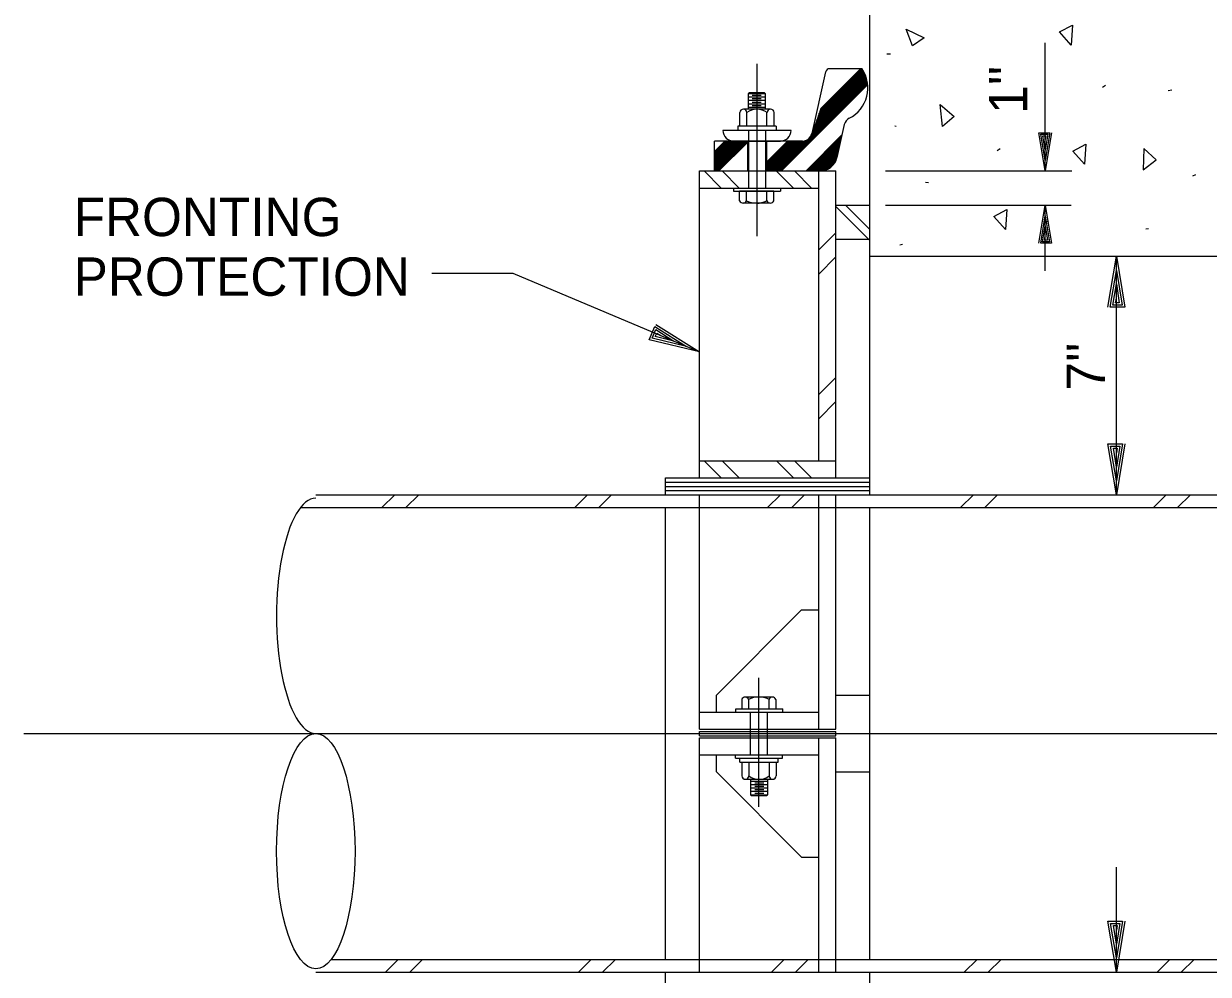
# Model space of a CAD drawing. Extents: x 22369.6 to 22389.4, y 22369.6 to 22386.
# Drawn here: x 22386.098 to 22387.546, y 22383.891 to 22385.053 of the extents above; entities that cross this region are included whole.
import ezdxf

# ---------------------------------------------------------------- set-up
doc = ezdxf.new("R2010")
doc.units = 0
for name, color, linetype in [('Level 1', 7, 'Continuous'), ('Level 2', 7, 'Continuous'), ('Level 4', 7, 'Continuous'), ('Level 44', 7, 'Continuous'), ('Level 50', 7, 'Continuous'), ('Level 7', 7, 'Continuous')]:
    doc.layers.add(name, color=color, linetype=linetype)

msp = doc.modelspace()

# ---------------------------------------------------------------- linework, layer by layer
at = {"layer": 'Level 1'}
for p, q in [((22387.3466, 22384.873), (22387.3466, 22385.0298)), ((22386.9944, 22385.0039), (22386.9944, 22384.7933)), ((22387.1271, 22384.9894), (22387.0643, 22384.9266)), ((22387.1269, 22384.9901), (22387.0648, 22384.928)), ((22387.1266, 22384.9908), (22387.0653, 22384.9294)), ((22387.1263, 22384.9914), (22387.0658, 22384.9309)), ((22387.126, 22384.992), (22387.0663, 22384.9323)), ((22387.1257, 22384.9927), (22387.0668, 22384.9337)), ((22387.1254, 22384.9933), (22387.0673, 22384.9352)), ((22387.1251, 22384.9939), (22387.0678, 22384.9366)), ((22387.1248, 22384.9945), (22387.0683, 22384.938)), ((22387.1245, 22384.9951), (22387.0688, 22384.9394)), ((22387.1241, 22384.9957), (22387.0693, 22384.9408)), ((22387.1238, 22384.9962), (22387.0698, 22384.9423)), ((22387.1234, 22384.9968), (22387.0703, 22384.9437)), ((22387.1231, 22384.9974), (22387.0708, 22384.9451)), ((22387.1227, 22384.9979), (22387.0713, 22384.9465)), ((22387.1219, 22384.998), (22387.0718, 22384.948)), ((22387.121, 22384.998), (22387.0723, 22384.9494)), ((22387.129, 22384.9832), (22387.0188, 22384.873)), ((22387.1291, 22384.9826), (22387.0195, 22384.873)), ((22387.1292, 22384.982), (22387.0202, 22384.873)), ((22387.1293, 22384.9814), (22387.0209, 22384.873)), ((22387.1294, 22384.9808), (22387.0216, 22384.873)), ((22387.1295, 22384.9802), (22387.0223, 22384.873)), ((22387.1296, 22384.9796), (22387.023, 22384.873)), ((22387.1296, 22384.9789), (22387.0237, 22384.873)), ((22387.1297, 22384.9783), (22387.0244, 22384.873)), ((22387.1288, 22384.9838), (22387.0596, 22384.9146)), ((22387.1287, 22384.9845), (22387.0608, 22384.9167)), ((22387.1285, 22384.9853), (22387.0613, 22384.9181)), ((22387.1283, 22384.986), (22387.0618, 22384.9195)), ((22387.1281, 22384.9867), (22387.0623, 22384.9209)), ((22387.1279, 22384.9874), (22387.0628, 22384.9223)), ((22387.1276, 22384.9881), (22387.0633, 22384.9238)), ((22387.1274, 22384.9888), (22387.0638, 22384.9252)), ((22386.984, 22384.9672), (22386.9851, 22384.9684)), ((22387.0049, 22384.9673), (22386.984, 22384.9673)), ((22386.984, 22384.9485), (22386.984, 22384.9672)), ((22387.0049, 22384.9631), (22386.984, 22384.9631)), ((22387.0038, 22384.9684), (22386.9851, 22384.9684)), ((22386.9996, 22384.9652), (22386.9887, 22384.9652)), ((22386.9996, 22384.9611), (22386.9887, 22384.9611)), ((22387.0049, 22384.9673), (22387.0038, 22384.9684)), ((22387.0049, 22384.9485), (22387.0049, 22384.9673)), ((22387.011, 22384.9485), (22386.9778, 22384.9485)), ((22387.0049, 22384.959), (22386.984, 22384.959)), ((22387.0049, 22384.9548), (22386.984, 22384.9548)), ((22387.0049, 22384.9506), (22386.984, 22384.9506)), ((22386.9996, 22384.9569), (22386.9887, 22384.9569)), ((22386.9996, 22384.9527), (22386.9887, 22384.9527)), ((22386.9736, 22384.9277), (22386.9736, 22384.9444)), ((22386.9736, 22384.9444), (22386.9736, 22384.9444)), ((22386.982, 22384.9277), (22386.982, 22384.9444)), ((22387.0067, 22384.9277), (22387.0067, 22384.9444)), ((22387.0153, 22384.9277), (22387.0153, 22384.9444)), ((22387.0179, 22384.9277), (22386.971, 22384.9277)), ((22386.971, 22384.9277), (22386.971, 22384.9225)), ((22386.984, 22384.9225), (22386.984, 22384.8522)), ((22387.0049, 22384.9225), (22387.0049, 22384.8522)), ((22387.0179, 22384.9277), (22387.0179, 22384.9225)), ((22387.0544, 22384.873), (22387.0983, 22384.917)), ((22386.9785, 22384.9095), (22386.9424, 22384.8734)), ((22386.9778, 22384.9095), (22386.9424, 22384.8741)), ((22386.9771, 22384.9095), (22386.9424, 22384.8748)), ((22386.9764, 22384.9095), (22386.9424, 22384.8755)), ((22386.9757, 22384.9095), (22386.9424, 22384.8762)), ((22386.975, 22384.9095), (22386.9424, 22384.8769)), ((22386.9743, 22384.9095), (22386.9424, 22384.8776)), ((22386.9735, 22384.9095), (22386.9424, 22384.8783)), ((22386.9728, 22384.9095), (22386.9424, 22384.879)), ((22386.9721, 22384.9095), (22386.9424, 22384.8797)), ((22386.9714, 22384.9095), (22386.9424, 22384.8804)), ((22386.9707, 22384.9095), (22386.9424, 22384.8811)), ((22386.97, 22384.9095), (22386.9424, 22384.8818)), ((22386.9693, 22384.9095), (22386.9424, 22384.8826)), ((22386.9686, 22384.9095), (22386.9424, 22384.8833)), ((22386.9679, 22384.9095), (22386.9424, 22384.884)), ((22386.9672, 22384.9095), (22386.9424, 22384.8847)), ((22386.9665, 22384.9095), (22386.9424, 22384.8854)), ((22386.9658, 22384.9095), (22386.9424, 22384.8861)), ((22386.9651, 22384.9095), (22386.9424, 22384.8868)), ((22386.9644, 22384.9095), (22386.9424, 22384.8875)), ((22386.9637, 22384.9095), (22386.9424, 22384.8882)), ((22386.9629, 22384.9095), (22386.9424, 22384.8889)), ((22386.9622, 22384.9095), (22386.9424, 22384.8896)), ((22386.9615, 22384.9095), (22386.9424, 22384.8903)), ((22386.9608, 22384.9095), (22386.9424, 22384.891)), ((22386.9601, 22384.9095), (22386.9424, 22384.8917)), ((22386.9594, 22384.9095), (22386.9424, 22384.8924)), ((22386.9587, 22384.9095), (22386.9424, 22384.8932)), ((22386.958, 22384.9095), (22386.9424, 22384.8939)), ((22386.9573, 22384.9095), (22386.9424, 22384.8946)), ((22386.9566, 22384.9095), (22386.9424, 22384.8953)), ((22386.9559, 22384.9095), (22386.9424, 22384.896)), ((22386.9552, 22384.9095), (22386.9424, 22384.8967)), ((22386.9792, 22384.9095), (22386.9428, 22384.873)), ((22386.9799, 22384.9095), (22386.9435, 22384.873)), ((22386.9806, 22384.9095), (22386.9442, 22384.873)), ((22386.9813, 22384.9095), (22386.9449, 22384.873)), ((22386.982, 22384.9095), (22386.9456, 22384.873)), ((22386.9827, 22384.9095), (22386.9463, 22384.873)), ((22386.9827, 22384.9088), (22386.947, 22384.873)), ((22386.9827, 22384.9081), (22386.9477, 22384.873)), ((22386.9827, 22384.908), (22386.9477, 22384.873)), ((22387.0425, 22384.9095), (22387.0061, 22384.873)), ((22387.0418, 22384.9095), (22387.0062, 22384.8739)), ((22387.0411, 22384.9095), (22387.0062, 22384.8746)), ((22387.0404, 22384.9095), (22387.0062, 22384.8753)), ((22387.0397, 22384.9095), (22387.0062, 22384.876)), ((22387.039, 22384.9095), (22387.0062, 22384.8767)), ((22387.0383, 22384.9095), (22387.0062, 22384.8774)), ((22387.0376, 22384.9095), (22387.0062, 22384.8781)), ((22387.0369, 22384.9095), (22387.0062, 22384.8788)), ((22387.0362, 22384.9095), (22387.0062, 22384.8795)), ((22387.0354, 22384.9095), (22387.0062, 22384.8802)), ((22387.0347, 22384.9095), (22387.0062, 22384.8809)), ((22387.034, 22384.9095), (22387.0062, 22384.8816)), ((22387.0333, 22384.9095), (22387.0062, 22384.8823)), ((22387.0326, 22384.9095), (22387.0062, 22384.883)), ((22387.0319, 22384.9095), (22387.0062, 22384.8837)), ((22387.0432, 22384.9095), (22387.0068, 22384.873)), ((22387.0439, 22384.9095), (22387.0075, 22384.873)), ((22387.0446, 22384.9095), (22387.0082, 22384.873)), ((22387.0454, 22384.9095), (22387.0089, 22384.873)), ((22387.0461, 22384.9095), (22387.0096, 22384.873)), ((22387.0468, 22384.9095), (22387.0103, 22384.873)), ((22387.0475, 22384.9095), (22387.011, 22384.873)), ((22387.0482, 22384.9095), (22387.0117, 22384.873)), ((22387.0489, 22384.9095), (22387.0124, 22384.873)), ((22387.0496, 22384.9095), (22387.0131, 22384.873)), ((22387.0503, 22384.9095), (22387.0138, 22384.873)), ((22387.051, 22384.9095), (22387.0145, 22384.873)), ((22387.0517, 22384.9095), (22387.0153, 22384.873)), ((22387.0528, 22384.9098), (22387.016, 22384.873)), ((22387.0538, 22384.9101), (22387.0167, 22384.873)), ((22387.0549, 22384.9106), (22387.0174, 22384.873)), ((22387.0566, 22384.9116), (22387.0181, 22384.873)), ((22387.0551, 22384.873), (22387.0981, 22384.9161)), ((22387.0558, 22384.873), (22387.0979, 22384.9152)), ((22387.0565, 22384.873), (22387.0977, 22384.9143)), ((22387.0572, 22384.873), (22387.0975, 22384.9133)), ((22387.0579, 22384.873), (22387.0973, 22384.9124)), ((22387.0586, 22384.873), (22387.0971, 22384.9115)), ((22387.0593, 22384.873), (22387.0969, 22384.9106)), ((22387.06, 22384.873), (22387.0967, 22384.9097)), ((22387.0607, 22384.873), (22387.0965, 22384.9088)), ((22387.0614, 22384.873), (22387.0963, 22384.9079)), ((22387.0621, 22384.873), (22387.0961, 22384.907)), ((22387.0628, 22384.873), (22387.0956, 22384.9058)), ((22387.0635, 22384.873), (22387.0957, 22384.9051)), ((22387.0643, 22384.873), (22387.0954, 22384.9042)), ((22387.065, 22384.873), (22387.0952, 22384.9033)), ((22387.0657, 22384.873), (22387.095, 22384.9024)), ((22387.0664, 22384.873), (22387.0948, 22384.9015)), ((22387.0671, 22384.873), (22387.0946, 22384.9006)), ((22387.0944, 22384.8997), (22387.0678, 22384.873)), ((22387.0942, 22384.8988), (22387.0685, 22384.873)), ((22387.094, 22384.8979), (22387.0692, 22384.873)), ((22387.0938, 22384.8969), (22387.0699, 22384.873)), ((22387.0936, 22384.896), (22387.0706, 22384.873)), ((22387.0934, 22384.8951), (22387.0714, 22384.8731)), ((22387.0932, 22384.8942), (22387.072, 22384.873)), ((22387.093, 22384.8933), (22387.0728, 22384.8731)), ((22387.0928, 22384.8924), (22387.0735, 22384.8731)), ((22387.0926, 22384.8915), (22387.0743, 22384.8732)), ((22387.0924, 22384.8906), (22387.0751, 22384.8733)), ((22387.0922, 22384.8896), (22387.076, 22384.8735)), ((22387.092, 22384.8887), (22387.0769, 22384.8737)), ((22387.0917, 22384.8878), (22387.0779, 22384.8739)), ((22387.0913, 22384.8867), (22387.079, 22384.8743)), ((22387.0907, 22384.8851), (22387.0805, 22384.875)), ((22387.0897, 22384.8832), (22387.0825, 22384.876)), ((22386.9506, 22384.8522), (22386.9298, 22384.873)), ((22386.9727, 22384.8522), (22386.9519, 22384.873)), ((22387.039, 22384.8522), (22387.0181, 22384.873)), ((22387.0611, 22384.8522), (22387.0402, 22384.873)), ((22387.1513, 22384.873), (22387.3791, 22384.873)), ((22386.9658, 22384.8522), (22386.9658, 22384.8483)), ((22386.9658, 22384.8483), (22387.0231, 22384.8483)), ((22387.015, 22384.8483), (22386.9733, 22384.8483)), ((22386.9733, 22384.8365), (22386.9733, 22384.8483)), ((22386.9817, 22384.8365), (22386.9817, 22384.8483)), ((22387.0064, 22384.8364), (22387.0064, 22384.8483)), ((22387.015, 22384.8365), (22387.015, 22384.8483)), ((22387.0231, 22384.8522), (22387.0231, 22384.8483)), ((22387.0107, 22384.8337), (22386.9775, 22384.8337)), ((22387.1325, 22384.8016), (22387.1027, 22384.8314)), ((22387.1513, 22384.8314), (22387.3783, 22384.8314)), ((22387.3466, 22384.7511), (22387.3466, 22384.8314)), ((22387.1325, 22384.7879), (22387.0908, 22384.8296)), ((22387.07, 22384.7765), (22387.0908, 22384.7973)), ((22387.07, 22384.747), (22387.0908, 22384.7679)), ((22387.4336, 22384.4772), (22387.4336, 22384.7689)), ((22387.07, 22384.5997), (22387.0908, 22384.6205)), ((22387.07, 22384.5702), (22387.0908, 22384.5911)), ((22386.9506, 22384.498), (22386.9298, 22384.5189)), ((22386.9727, 22384.498), (22386.9519, 22384.5189)), ((22387.039, 22384.498), (22387.0182, 22384.5189)), ((22387.061, 22384.498), (22387.0402, 22384.5189)), ((22386.8825, 22384.4928), (22387.1325, 22384.4928)), ((22386.8825, 22384.4876), (22387.1325, 22384.4876)), ((22386.5362, 22384.4616), (22386.5518, 22384.4772)), ((22386.5656, 22384.4616), (22386.5812, 22384.4772)), ((22386.7718, 22384.4616), (22386.7875, 22384.4772)), ((22386.8013, 22384.4616), (22386.8169, 22384.4772)), ((22386.8825, 22384.4824), (22387.1325, 22384.4824)), ((22387.0075, 22384.4616), (22387.0232, 22384.4772)), ((22387.037, 22384.4616), (22387.0526, 22384.4772)), ((22387.2433, 22384.4616), (22387.2589, 22384.4772)), ((22387.2727, 22384.4616), (22387.2883, 22384.4772)), ((22387.4789, 22384.4616), (22387.4946, 22384.4772)), ((22387.5084, 22384.4616), (22387.524, 22384.4772)), ((22386.9969, 22384.0958), (22386.9969, 22384.2534)), ((22386.9758, 22384.2272), (22386.9758, 22384.2155)), ((22387.0132, 22384.23), (22386.98, 22384.23)), ((22386.9842, 22384.2273), (22386.9842, 22384.2155)), ((22387.0089, 22384.2273), (22387.0089, 22384.2155)), ((22387.0175, 22384.2272), (22387.0175, 22384.2155)), ((22386.9686, 22384.2155), (22387.0259, 22384.2155)), ((22386.9686, 22384.2116), (22386.9686, 22384.2155)), ((22386.9865, 22384.1595), (22386.9865, 22384.2116)), ((22387.0074, 22384.1595), (22387.0074, 22384.2116)), ((22387.0259, 22384.2116), (22387.0259, 22384.2155)), ((22386.0985, 22384.1855), (22388.9892, 22384.1855)), ((22386.9241, 22384.1881), (22387.0908, 22384.1881)), ((22386.9241, 22384.1829), (22386.9241, 22384.1881)), ((22386.9241, 22384.1829), (22387.0908, 22384.1829)), ((22387.0908, 22384.1829), (22387.0908, 22384.1881)), ((22386.9683, 22384.1556), (22386.9683, 22384.1595)), ((22386.9683, 22384.1556), (22387.0256, 22384.1556)), ((22386.9735, 22384.1504), (22386.9735, 22384.1556)), ((22386.9735, 22384.1504), (22387.0204, 22384.1504)), ((22386.9761, 22384.1504), (22386.9761, 22384.1337)), ((22386.9847, 22384.1504), (22386.9847, 22384.1337)), ((22387.0094, 22384.1504), (22387.0094, 22384.1337)), ((22387.0178, 22384.1504), (22387.0178, 22384.1337)), ((22387.0204, 22384.1504), (22387.0204, 22384.1556)), ((22387.0256, 22384.1556), (22387.0256, 22384.1595)), ((22386.9804, 22384.1296), (22387.0136, 22384.1296)), ((22386.9865, 22384.1296), (22386.9865, 22384.1108)), ((22386.9865, 22384.1274), (22387.0074, 22384.1274)), ((22386.9865, 22384.1233), (22387.0074, 22384.1233)), ((22386.9918, 22384.1253), (22387.0027, 22384.1253)), ((22386.9918, 22384.1212), (22387.0027, 22384.1212)), ((22387.0074, 22384.1296), (22387.0074, 22384.1109)), ((22386.9865, 22384.1191), (22387.0074, 22384.1191)), ((22386.9865, 22384.1149), (22387.0074, 22384.1149)), ((22386.9865, 22384.1108), (22386.9876, 22384.1097)), ((22386.9865, 22384.1108), (22387.0074, 22384.1108)), ((22386.9876, 22384.1097), (22387.0063, 22384.1097)), ((22386.9918, 22384.117), (22387.0027, 22384.117)), ((22386.9918, 22384.1128), (22387.0027, 22384.1128)), ((22387.0074, 22384.1109), (22387.0063, 22384.1097)), ((22387.4336, 22383.8939), (22387.4336, 22384.0223)), ((22386.5406, 22383.8939), (22386.5562, 22383.9095)), ((22386.5701, 22383.8939), (22386.5857, 22383.9095)), ((22386.7763, 22383.8939), (22386.7919, 22383.9095)), ((22386.8058, 22383.8939), (22386.8214, 22383.9095)), ((22387.012, 22383.8939), (22387.0276, 22383.9095)), ((22387.0414, 22383.8939), (22387.0571, 22383.9095)), ((22387.2477, 22383.8939), (22387.2633, 22383.9095)), ((22387.2771, 22383.8939), (22387.2928, 22383.9095)), ((22387.4834, 22383.8939), (22387.499, 22383.9095)), ((22387.5128, 22383.8939), (22387.5285, 22383.9095))]:
    msp.add_line(p, q, dxfattribs=at)
for centre, radius, start, end in [((22386.9778, 22384.9443), 0.00421, 0.4975, 179.5025), ((22386.9944, 22384.9282), 0.0203, 52.4343, 127.5657), ((22387.0111, 22384.9443), 0.00422, 0.5659, 179.4342), ((22386.9775, 22384.8383), 0.00456, 202.8005, 337.625), ((22386.9941, 22384.8622), 0.0285, 244.116, 295.4481), ((22387.0107, 22384.8384), 0.00469, 204.0009, 336.8325), ((22386.98, 22384.2255), 0.00456, 22.375, 157.1995), ((22386.9966, 22384.2016), 0.0285, 64.5519, 115.884), ((22387.0132, 22384.2254), 0.00469, 23.1675, 155.9991), ((22386.9803, 22384.1338), 0.00422, 180.5659, 359.4341), ((22386.997, 22384.1498), 0.0203, 232.4343, 307.5657), ((22387.0136, 22384.1338), 0.00421, 180.4975, 359.5025)]:
    msp.add_arc(centre, radius, start, end, dxfattribs=at)
msp.add_ellipse((22386.4554, 22384.3293), major_axis=(0, 0.1438), ratio=0.333333, start_param=0, end_param=3.141593, dxfattribs=at)
msp.add_ellipse((22386.4554, 22384.0418), major_axis=(0, -0.1438), ratio=0.333333, dxfattribs=at)
at = {"layer": 'Level 2'}
for p, q in [((22387.0782, 22384.994), (22387.0613, 22384.9187)), ((22387.1227, 22384.998), (22387.0833, 22384.998)), ((22387.0361, 22384.9225), (22386.9528, 22384.9225)), ((22387.1011, 22384.9297), (22387.0921, 22384.8893)), ((22387.0499, 22384.9095), (22386.9424, 22384.9095)), ((22386.9424, 22384.873), (22386.9424, 22384.9095)), ((22386.9658, 22384.9095), (22387.0231, 22384.9095)), ((22386.9827, 22384.9095), (22386.9827, 22384.873)), ((22387.0062, 22384.9095), (22387.0062, 22384.873)), ((22387.3466, 22384.886), (22387.3466, 22384.886)), ((22386.9241, 22384.873), (22387.0908, 22384.873)), ((22386.9241, 22384.498), (22386.9241, 22384.873)), ((22386.9424, 22384.873), (22387.0718, 22384.873)), ((22387.07, 22384.5189), (22387.07, 22384.873)), ((22387.0908, 22384.498), (22387.0908, 22384.873)), ((22387.3466, 22384.873), (22387.3466, 22384.873)), ((22386.9241, 22384.8522), (22387.07, 22384.8522)), ((22387.0908, 22384.8314), (22387.1325, 22384.8314)), ((22387.1325, 22384.4772), (22387.1325, 22384.8314)), ((22387.3466, 22384.8314), (22387.3466, 22384.8314)), ((22387.3466, 22384.8184), (22387.3466, 22384.8184)), ((22387.0908, 22384.7897), (22387.1325, 22384.7897)), ((22387.4336, 22384.7689), (22387.4336, 22384.7689)), ((22387.4336, 22384.7515), (22387.4336, 22384.7515)), ((22386.9082, 22384.6586), (22386.9082, 22384.6586)), ((22386.9241, 22384.6518), (22386.9241, 22384.6518)), ((22386.9241, 22384.5189), (22387.0908, 22384.5189)), ((22386.8825, 22384.498), (22387.1325, 22384.498)), ((22386.8825, 22384.4772), (22386.8825, 22384.498)), ((22387.4336, 22384.4945), (22387.4336, 22384.4945)), ((22386.4554, 22384.4772), (22388.1846, 22384.4772)), ((22386.9241, 22384.1907), (22386.9241, 22384.4772)), ((22387.07, 22384.1907), (22387.07, 22384.4772)), ((22387.0908, 22384.1907), (22387.0908, 22384.4772)), ((22387.4336, 22384.4772), (22387.4336, 22384.4772)), ((22386.4366, 22384.4616), (22388.1658, 22384.4616)), ((22386.8825, 22383.9095), (22386.8825, 22384.4616)), ((22387.1325, 22383.9095), (22387.1325, 22384.4616)), ((22386.9449, 22384.2324), (22387.049, 22384.3366)), ((22387.049, 22384.3366), (22387.0699, 22384.3366)), ((22386.9449, 22384.2116), (22386.9449, 22384.2324)), ((22387.0908, 22384.2324), (22387.1325, 22384.2324)), ((22386.9241, 22384.2116), (22387.07, 22384.2116)), ((22386.9241, 22384.1907), (22387.0908, 22384.1907)), ((22386.9241, 22384.1803), (22387.0908, 22384.1803)), ((22386.9241, 22383.8939), (22386.9241, 22384.1803)), ((22387.07, 22383.8939), (22387.07, 22384.1803)), ((22387.0908, 22383.8939), (22387.0908, 22384.1803)), ((22386.9241, 22384.1595), (22387.07, 22384.1595)), ((22386.9449, 22384.1387), (22386.9449, 22384.1595)), ((22386.9449, 22384.1387), (22387.049, 22384.0345)), ((22387.0908, 22384.1387), (22387.1325, 22384.1387)), ((22387.049, 22384.0345), (22387.0699, 22384.0345)), ((22386.4741, 22383.9095), (22388.2033, 22383.9095)), ((22387.4336, 22383.9112), (22387.4336, 22383.9112)), ((22386.4554, 22383.8939), (22388.1846, 22383.8939)), ((22386.8825, 22383.873), (22386.8825, 22383.8939)), ((22387.1325, 22383.5397), (22387.1325, 22383.8939)), ((22387.4336, 22383.8939), (22387.4336, 22383.8939))]:
    msp.add_line(p, q, dxfattribs=at)
for points in [[(22387.3544, 22384.9198), (22387.3466, 22384.873), (22387.3389, 22384.9198), (22387.3521, 22384.9198), (22387.3466, 22384.886), (22387.3414, 22384.9178), (22387.3499, 22384.9178), (22387.3466, 22384.8985), (22387.3439, 22384.9158), (22387.3474, 22384.9158), (22387.3466, 22384.9115)], [(22387.3389, 22384.7846), (22387.3466, 22384.8314), (22387.3544, 22384.7846), (22387.3411, 22384.7846), (22387.3466, 22384.8184), (22387.3519, 22384.7866), (22387.3434, 22384.7866), (22387.3466, 22384.8059), (22387.3494, 22384.7886), (22387.3459, 22384.7886), (22387.3466, 22384.7929)], [(22387.4232, 22384.7065), (22387.4336, 22384.7689), (22387.4439, 22384.7065), (22387.4262, 22384.7065), (22387.4336, 22384.7515), (22387.4406, 22384.7092), (22387.4292, 22384.7092), (22387.4336, 22384.7349), (22387.4372, 22384.7119), (22387.4326, 22384.7119), (22387.4336, 22384.7175)], [(22386.5973, 22384.7483), (22386.6963, 22384.7483), (22386.9241, 22384.6518)], [(22386.8708, 22384.6856), (22386.9241, 22384.6518), (22386.8627, 22384.6666), (22386.8696, 22384.6829), (22386.9082, 22384.6586), (22386.8665, 22384.6686), (22386.8709, 22384.6791), (22386.8928, 22384.6651), (22386.8702, 22384.6707), (22386.872, 22384.675), (22386.8769, 22384.6718)], [(22387.4439, 22384.5395), (22387.4336, 22384.4772), (22387.4232, 22384.5395), (22387.4409, 22384.5395), (22387.4336, 22384.4945), (22387.4266, 22384.5369), (22387.4379, 22384.5369), (22387.4336, 22384.5112), (22387.4299, 22384.5342), (22387.4346, 22384.5342), (22387.4336, 22384.5285)], [(22387.4439, 22383.9562), (22387.4336, 22383.8939), (22387.4232, 22383.9562), (22387.4409, 22383.9562), (22387.4336, 22383.9112), (22387.4266, 22383.9535), (22387.4379, 22383.9535), (22387.4336, 22383.9279), (22387.4299, 22383.9509), (22387.4346, 22383.9509), (22387.4336, 22383.9452)]]:
    msp.add_lwpolyline(points, dxfattribs=at)
for centre, radius, start, end in [((22387.0833, 22384.9928), 0.00521, 90, 167.3821), ((22387.0882, 22384.9746), 0.0417, 297.1705, 34.2289), ((22387.1126, 22384.9271), 0.0117, 117.1705, 167.3835), ((22386.9658, 22384.9225), 0.013, 180, 270), ((22387.0231, 22384.9225), 0.013, 270, 0), ((22387.0499, 22384.9212), 0.0117, 270, 347.3806), ((22387.0718, 22384.8939), 0.0208, 270, 347.3827)]:
    msp.add_arc(centre, radius, start, end, dxfattribs=at)
at = {"layer": 'Level 44'}
for p, q in [((22387.1531, 22385.0163), (22387.1576, 22385.0163)), ((22387.4165, 22384.9755), (22387.4202, 22384.9778)), ((22387.497, 22384.9713), (22387.5013, 22384.972)), ((22387.163, 22384.9282), (22387.1645, 22384.9278)), ((22387.2879, 22384.8982), (22387.2916, 22384.9004)), ((22387.2005, 22384.8592), (22387.2042, 22384.8589)), ((22387.5271, 22384.8672), (22387.5307, 22384.8689)), ((22387.3468, 22384.8101), (22387.3505, 22384.8124)), ((22387.4696, 22384.8024), (22387.4729, 22384.8027)), ((22387.1689, 22384.7829), (22387.1722, 22384.7835))]:
    msp.add_line(p, q, dxfattribs=at)
for points in [[(22387.3784, 22385.0269), (22387.3641, 22385.0429), (22387.38, 22385.0514)], [(22387.1846, 22385.026), (22387.1767, 22385.0464), (22387.1988, 22385.0357)], [(22387.2184, 22384.9543), (22387.2355, 22384.9394), (22387.2213, 22384.9274)], [(22387.3945, 22384.8814), (22387.3802, 22384.8974), (22387.3961, 22384.9059)], [(22387.4664, 22384.8746), (22387.4824, 22384.8867), (22387.4671, 22384.9003)], [(22387.298, 22384.8013), (22387.2838, 22384.8173), (22387.2997, 22384.8258)]]:
    msp.add_lwpolyline(points, close=True, dxfattribs=at)
at = {"layer": 'Level 50'}
msp.add_line((22387.0178, 22384.1337), (22387.0178, 22384.1337), dxfattribs=at)
at = {"layer": 'Level 7'}
for p, q in [((22387.1325, 22384.4772), (22387.1325, 22385.8855)), ((22387.1325, 22384.7689), (22387.6325, 22384.7689)), ((22387.1325, 22383.9095), (22387.1325, 22384.4616)), ((22387.1325, 22382.184), (22387.1325, 22383.8939))]:
    msp.add_line(p, q, dxfattribs=at)

# ---------------------------------------------------------------- texts
at = {"layer": 'Level 4'}
for s, p in [("1''", (22387.3247, 22384.9429)), ("7''", (22387.4197, 22384.6046))]:
    msp.add_text(s, height=0.04688, rotation=90, dxfattribs=at).set_placement(p)
for s, p in [('FRONTING', (22386.1595, 22384.7934)), ('PROTECTION', (22386.1595, 22384.7205))]:
    msp.add_text(s, height=0.04688, dxfattribs=at).set_placement(p)

doc.saveas('drawing.dxf')
